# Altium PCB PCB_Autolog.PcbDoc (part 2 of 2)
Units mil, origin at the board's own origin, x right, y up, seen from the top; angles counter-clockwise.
Board outline 3847.36 x 2641.73 mil, 2 copper layers (Top Layer, Bottom Layer); 80 components, 62 nets, 278 pads, 180 vias.
Unrouted connection lines stored in the file: 64.
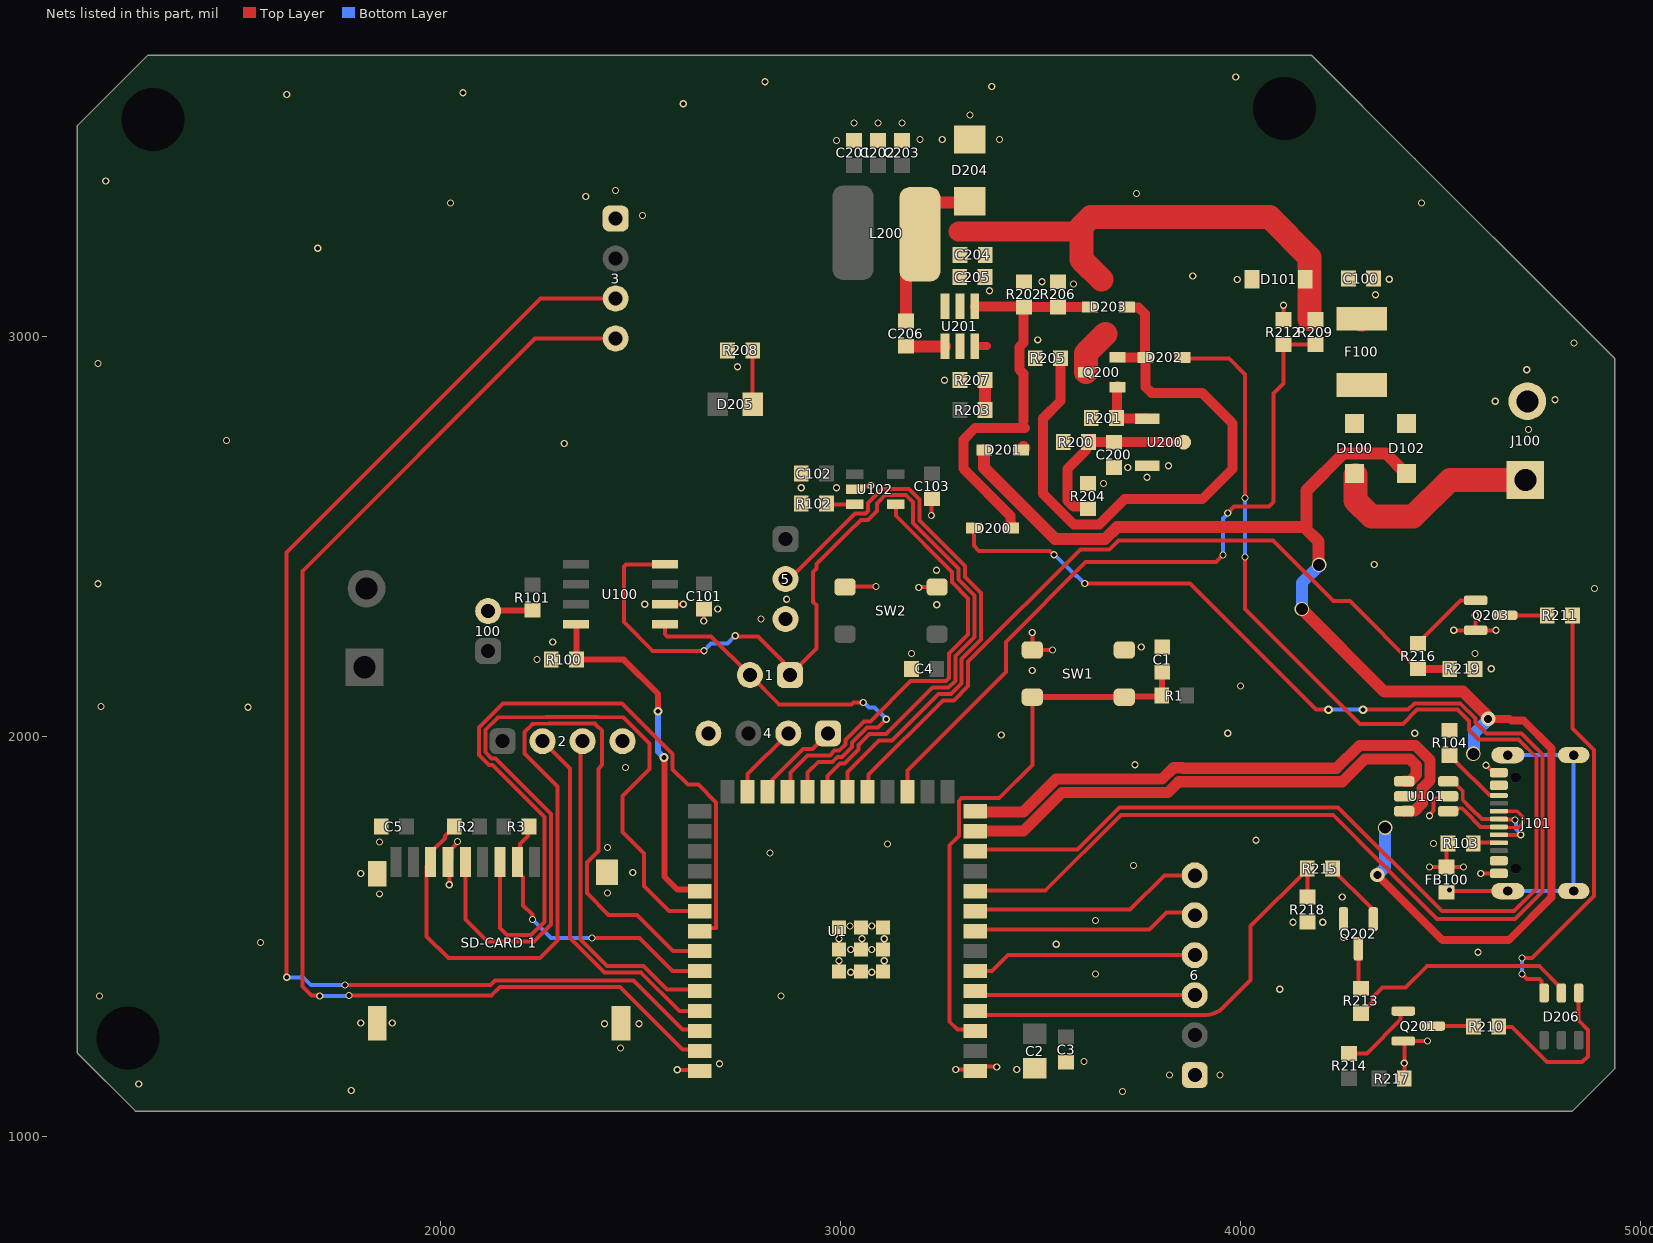
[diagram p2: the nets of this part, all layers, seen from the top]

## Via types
v1: diameter 18, hole 12, Top Layer to Bottom Layer, tented both sides, 162 vias
v2: diameter 22, hole 12, Top Layer to Bottom Layer, tented both sides, 8 vias
v3: diameter 36, hole 30, Top Layer to Bottom Layer, tented both sides, 7 vias
v4: diameter 36, hole 20, Top Layer to Bottom Layer, tented both sides, 2 vias
v5: diameter 37, hole 30, Top Layer to Bottom Layer, tented both sides, 1 vias

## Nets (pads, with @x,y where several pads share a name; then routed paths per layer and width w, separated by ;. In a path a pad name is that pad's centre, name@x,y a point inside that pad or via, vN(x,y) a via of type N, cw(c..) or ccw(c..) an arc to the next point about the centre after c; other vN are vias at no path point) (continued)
CAN_RS: R100.2 U1.31 U100.8 | length 894.3
  Top Layer w15: U100.8@2337.73,2280.71 2338.98,2279.46 R100.2@2338.98,2192.21 2457.39,2192.21 2543.31,2106.3 v2(2543.31,2062.99) ; v2(2557.78,1947.54) 2558.92,1946.4 2558.92,1649.74 2591.73,1616.93 U1.31@2647.64,1616.93
  Bottom Layer w15: v2(2543.31,2062.99) 2543.31,1962.01 v2(2557.78,1947.54)
CAN_RX: 1.1 U1.21 U100.4 | length 2389.2
  Top Layer w10: U100.4@2560.23,2430.71 2463.25,2430.71 2457.39,2424.85 2457.39,2286.7 2529.66,2214.44 v1(2658.21,2214.44) ; v1(2736.22,2251.97) 2737.75,2250.44 2792.87,2250.44 2856.17,2187.14 2856.17,2170.21 1.1@2872.83,2153.54 2939.66,2220.37 2939.66,2328.35 2931.25,2336.75 2931.25,2411.28 2939.66,2419.69 2939.66,2431.73 3015.85,2507.92 3016.4,2507.92 3050.38,2541.9 3068.27,2541.9 3090.55,2564.18 3090.55,2582.68 3111.4,2603.52 3164.01,2603.52 3181.35,2586.18 3181.35,2533.51 3294.72,2420.14 3294.72,2392.51 3334.9,2352.33 3334.9,2248.97 3286.84,2200.91 3286.84,2139.29 3269.85,2122.29 3229.53,2122.29 3113.3,2006.06 3071.95,2006.06 3044.4,1978.5 3044.4,1967.08 3009.69,1932.37 2998.27,1932.37 2967.13,1901.23 U1.21@2967.13,1866.14
  Bottom Layer w10: v1(2658.21,2214.44) 2676.05,2232.28 2716.54,2232.28 v1(2736.22,2251.97)
CAN_TX: 1.2 U1.22 U100.1 | length 973.3
  Top Layer w10: U100.1@2560.23,2280.71 2560.23,2256.3 2566.09,2250.44 2675.94,2250.44 1.2@2772.83,2153.54 2846.32,2080.06 3027.59,2080.06 3032.59,2085.06 3056.43,2085.06 v1(3056.59,2085.22) ; U1.22@2917.13,1866.14 2917.13,1909.45 2944.43,1936.76 2980.03,1936.76 2991.64,1948.37 3003.06,1948.37 3028.4,1973.71 3028.4,1985.13 3065.33,2022.06 3092.92,2022.06 v1(3114.17,2043.31)
  Bottom Layer w10: v1(3056.59,2085.22) 3058.76,2085.22 3071.43,2072.55 3084.93,2072.55 v1(3114.17,2043.31)
FORCE_ON: D200.2 U1.10 | length 3680.4
  Top Layer w10: D200.2@3333.74,2521 3333.74,2477.28 3346.46,2464.57 3523.62,2464.57 v1(3533.6,2454.59) ; U1.10@3336.61,1616.93 3339.37,1614.17 3511.81,1614.17 3700.79,1803.15 4232.28,1803.15 4352.89,1682.54 4354.53,1682.54 4371.52,1665.56 4371.52,1663.91 4492.38,1543.06 4686.95,1543.06 4756.16,1612.27 4756.16,1954.66 4702.95,2007.87 4615.1,2007.87 4588.04,2034.94 4588.04,2044.91 4550.02,2082.93 4435.44,2082.93 4419.44,2066.93 v2(4307.09,2066.93) ; v1(3610.55,2382.39) 3873.52,2382.39 4188.98,2066.93 v2(4220.47,2066.93)
  Bottom Layer w10: v1(3533.6,2454.59) 3535.57,2454.59 3588.65,2401.5 3591.44,2401.5 v1(3610.55,2382.39) ; v2(4220.47,2066.93) v2(4307.09,2066.93)
GND: 2.4 3.1 4.4 5.3 6.1 "SD-CARD 1.6" "SD-CARD 1.10" "SD-CARD 1.11" "SD-CARD 1.12" "SD-CARD 1.13" C1.2 C2.2 C3.2 C4.1 C5.1 C100.1 C101.1 C102.2 C103.2 C200.2 C201.2 C202.2 C203.2 C204.2 C205.2 D101.2 D204.2 FB100.1 J100.2 j101.A1/B12 j101.B1/A12 Q201.2 Q202.2 Q203.2 R100.1 R102.1 R103.1 R104.2 R204.1 R205.1 R206.1 R207.1 R208.2 R212.1 R217.2 R218.1 R219.1 SW1.2 SW2.2 U1.1 U1.40 U1.41 U1.42 U1.43 U1.44 U1.45 U1.46 U1.47 U1.48 U1.49 U100.2 U101.2 U102.2 U200.3 U201.2 | length 1302.6
  Top Layer w10: v1(2020.83,1628.91) 2020.83,1682.92 2017.71,1686.03 2026.49,1694.81 2026.49,1718.43 2039.79,1731.72 2039.79,1735.68 v1(2041.32,1737.21) ; U100.2@2560.23,2330.71 v1(2606.24,2330.71) ; v1(2591,1166) 2641.83,1166 U1.40@2643.83,1164 ; v1(2657.48,2288.63) C101.1@2657.48,2318.9 ; SW2.2@3010.83,2374.02 3011.52,2374.7 3087.89,2374.7 v1(3088.58,2375.39) ; U102.2@3035.43,2618.11 3042.24,2624.92 3070.1,2624.92 3072.87,2627.7 v1(3075.04,2627.7) ; v1(3195.28,2372.77) 3195.9,2373.39 3240.52,2373.39 SW2.2@3241.14,2374.02 ; v1(3226.85,2552.57) 3226.85,2592.98 C103.2@3228.35,2594.48 ; v1(3287.83,1166.93) 3336.61,1166.93 3344.58,1174.9 3388.91,1174.9 v1(3390.58,1173.23) ; v1(3479.33,2260.24) 3479.33,2229.58 3492.38,2216.54 v1(3529.96,2216.54) ; R212.1@4107.48,3043.31 v1(4107.48,3078.71) ; R217.2@4410.04,1144.25 v1(4410.04,1182.75) 4410.04,1235.63 Q201.2@4407.48,1238.19 v1(4468.04,1238.19) ; v1(4472.77,1673.23) FB100.1@4515.75,1673.23 ; v1(4472.77,1801.76) 4472.77,1803.92 4483.09,1814.25 4483.09,1838.98 4489.17,1845.06 4514.35,1845.06 U101.2@4519.69,1850.39 ; R103.1@4519.68,1732.28 4515.75,1728.35 FB100.1@4515.75,1673.23 ; v1(4533.84,2265.75) Q203.2@4588.58,2265.75 ; v1(4558.18,1673.23) FB100.1@4515.75,1673.23 ; v1(4587.68,2303.15) 4587.68,2266.65 Q203.2@4588.58,2265.75 ; v1(4601.24,1657.48) j101.A1/B12@4646.56,1657.48 ; v1(4614.17,1928.25) 4626.72,1915.7 4640.3,1915.7 j101.B1/A12@4646.56,1909.45 ; v1(4639.76,2265.75) Q203.2@4588.58,2265.75
  other v1: 3705,1112 1775.59,1114.17 1244.09,1130.54 3822.83,1152.76 3948.61,1152.76 3440.35,1166.93 2696.85,1181.1 3609,1187 2448.82,1220.47 2409.09,1281.54 2495.7,1281.54 1799.21,1283.46 1877.95,1283.46 1145.67,1350.39 2850.39,1350.39 4098.43,1367.62 3637.8,1405.51 3025,1410 3077.9,1410 2996.06,1439 3109,1439 4594.56,1460.01 3025,1467 3077.9,1467 3539.37,1480.32 1548.42,1484.25 2996.06,1494 3053,1494 3109,1494 4257.87,1496.77 3023,1526 3077.9,1525.98 4131.32,1535.43 4205.82,1535.43 3637.8,1539.37 4254.82,1598.43 1846.46,1606.3 2416.96,1608.32 1799.21,1657.48 2479.95,1659.5 3732.34,1677.17 2822.83,1708.66 2416.6,1722.49 3117.13,1731.06 4483.09,1732.28 1846.46,1735.68 4039.37,1740.16 2461.39,1922.39 3736.22,1929.13 3401.57,2003.94 3968.5,2007.87 4436.18,2007.87 1517,2073 1149.61,2074.8 4000,2125.98 3479.33,2165.35 4627.63,2169.29 2240.16,2192.91 3177.16,2207.54 4586.62,2207.79 3751.91,2223.98 2279.59,2236.28 2801.02,2293.7 2692.32,2318.9 3240.16,2329.6 2509.64,2330.97 2864.85,2343.4 4885.83,2370.08 1141.73,2381.89 3239.94,2415.79 4334.72,2430.28 2901.57,2622.11 2989.54,2622.11 3657.27,2632.72 3766.35,2648.72 3718.41,2673.22 3820.22,2677.22 2308.62,2732.65 1463.62,2740.65 4720.54,2767.72 4637.8,2838.58 4787.4,2842.58 3259.84,2891.22 4716.54,2917.32 2741.65,2925.2 1141.73,2933.07 4834.65,2984.25 3492.87,2992.26 4338.36,3104.87 3372,3115 3582.45,3131.93 3503.94,3137.72 3992,3143 4372.2,3143.89 3880.69,3152.08 1691.62,3221.65 2503.94,3303.15 2023.62,3334.65 4452.76,3334.65 2362.2,3350.67 3740.16,3358.27 2437.01,3366.14 1161.42,3389.76 2989.42,3491.22 3198.27,3493.58 3254.34,3493.58 3397.64,3493.58 3033.27,3535.02 3093.27,3535.02 3153.27,3535.02 3323.27,3555.12 2606.3,3582.68 1614.17,3606.3 2055.12,3610.24 3377.95,3625.98 2811.02,3637.8 3988.19,3649.61
GPIO47: 4.1 U1.24 | length 218.6
  Top Layer w10: U1.24@2817.13,1866.14 2829.84,1878.86 2829.84,1892.65 2905.69,1968.5 2909.45,1968.5 2909.7,1968.76 2929.78,1968.76 4.1@2968.9,2007.87
GPIO48: 4.2 U1.25 | length 183.9
  Top Layer w10: U1.25@2767.13,1866.14 2767.13,1906.1 4.2@2868.9,2007.87
GPIO_5: 6.3 U1.5 | length 555.1
  Top Layer w10: U1.5@3336.61,1366.93 3349.33,1354.21 3365.54,1354.21 3367,1352.76 6.3@3885.83,1352.76
GPIO_6: 6.4 U1.6 | length 565.7
  Top Layer w10: U1.6@3336.61,1412.93 3379.15,1412.93 3418.98,1452.76 6.4@3885.83,1452.76
GPIO_12: 5.2 U1.20 | length 1417.1
  Top Layer w10: 5.2@2862.2,2393.7 2871.72,2393.7 3035.92,2557.9 3061.64,2557.9 3068.08,2564.34 3068.08,2583.83 3103.77,2619.52 3170.64,2619.52 3197.35,2592.81 3197.35,2540.14 3310.72,2426.77 3310.72,2399.14 3350.9,2358.96 3350.9,2242.34 3302.84,2194.28 3302.84,2132.66 3276.47,2106.29 3244.53,2106.29 3128.3,1990.06 3096.35,1990.06 3017.13,1910.83 U1.20@3017.13,1866.14
GPIO_15: 6.5 U1.8 | length 569.3
  Top Layer w10: U1.8@3336.61,1516.93 3772.83,1516.93 3814.96,1559.06 3879.53,1559.06 6.5@3885.83,1552.76
GPIO_16: 6.6 U1.9 | length 581.3
  Top Layer w10: U1.9@3340.12,1566.93 3724.41,1566.93 3810.24,1652.76 6.6@3885.83,1652.76
GREEN_LED: R215.1 R218.2 U1.4 | length 1134.6
  Top Layer w10: U1.4@3336.61,1316.93 3350.73,1302.81 3568.66,1303.44 cw(c3568.78,1262.91) 3575.9,1302.81 3906.55,1302.81 ccw(c3906.55,1382.85) 3948.61,1314.76 4025,1391.14 4025,1525.47 R215.1@4167.32,1667.79 ; R218.2@4167.32,1598.43 R215.1@4167.32,1667.79 ; R215.1@4167.32,1669.29 R215.1@4167.32,1667.79
H_DRIVER: U1.23 U102.4 | length 1077.3
  Top Layer w10: U1.23@2867.13,1866.14 2874.02,1873.03 2874.02,1909.45 2917.32,1952.76 2973.4,1952.76 2985.02,1964.37 2996.43,1964.37 3012.4,1980.34 3012.4,1991.75 3058.7,2038.06 3074.48,2038.06 3174.72,2138.29 3263.22,2138.29 3270.84,2145.92 3270.84,2207.54 3318.9,2255.59 3318.9,2345.71 3278.72,2385.89 3278.72,2411.66 3137.8,2552.57 U102.4@3137.8,2580.71
Net100_2: 100.2 R101.1 | length 111.7
  Top Layer w15: 100.2@2118.11,2313.78 2119.08,2314.75 2228.01,2314.75 R101.1@2228.98,2315.71
NetC1_1: C1.1 R1.1 SW1.1 U1.3 | length 1410.3
  Top Layer w10: U1.3@3336.61,1266.93 3292.13,1266.93 3271.65,1287.4 3271.65,1726.77 3296.09,1751.2 3296.09,1839.2 3302.53,1845.65 3370.7,1845.65 3370.86,1845.49 3396.67,1845.49 3479.33,1928.15 SW1.1@3479.33,2098.43
  Top Layer w15: SW1.1@3479.33,2098.43 SW1.1@3709.65,2098.43 3711.67,2100.45 3800.96,2100.45 R1.1@3802.99,2102.48 3803.74,2103.23 3803.74,2160.23 C1.1@3804.49,2160.98
NetC200_1: C200.1 R200.1 R204.2 U200.2 | length 466.2
  Top Layer w25: R204.2@3618.27,2569.72 3612.9,2575.09 3582.1,2575.09 3566.93,2590.26 3566.93,2669.29 3613.77,2716.13 3613.77,2730.22 R200.1@3619.77,2736.22 3629.92,2736.22 C200.1@3683.27,2736.22 U200.2@3858.27,2736.22
NetC206_1: C206.1 U201.1 | length 97.6
  Top Layer w30: C206.1@3163.27,2976.22 U201.1@3260.85,2976.24
NetC206_2: C206.2 D204.1 L200.1 U201.6 | length 416.9
  Top Layer w30: C206.2@3163.27,3039.22 3163.27,3148.56 3198.27,3183.56 L200.1@3198.27,3256.22 3198.27,3300.92 3233.64,3336.3 3320.71,3336.3 D204.1@3323.27,3338.86
NetD100_1: D100.1 D102.1 F100.2
NetD100_2: D100.2 J100.1 | length 543
  Top Layer w60: D100.2@4288.31,2653.7 4288.31,2589.84 4328.15,2550 4432.24,2550 4523.98,2641.73 J100.1@4712.91,2641.73
NetD200_1: D200.1 D201.1 D203.1 R202.1 R206.2 U201.4 | length 1013.6
  Top Layer w25: U201.4@3335.67,3076.19 3455.36,3076.19 R202.1@3456.8,3074.75 ; D200.1@3426.06,2521 3425.99,2522.28 3424.42,2552.4 3307,2669.82 3307,2742.37 3336.28,2771.65 3460.63,2771.65 ; 3456.8,2789.23 3456.8,2907.99 3447.27,2917.52 3447.27,2974.92 3456.8,2984.45 R202.1@3456.8,3071.22 ; R202.1@3458.27,3074.72 R206.2@3543.27,3074.72 D203.1@3620.08,3074.72
  Top Layer w30: D201.1@3456.8,2724.32 D201.1@3459.9,2721.22
NetD202_1: D202.1 D203.2 Q200.2 R205.2 | length 1594.2
  Top Layer w25: R205.2@3549.77,2946.22 3549.77,2839.07 3505.77,2795.07 3505.77,2607.58 3583.13,2530.22 3646.97,2530.22 3710.6,2593.85 3904.88,2593.85 3980.32,2669.29 3980.32,2783.46 3903.98,2859.8 3777.33,2859.8 3762.69,2874.44 D202.1@3762.69,2948.62 3761.41,2949.9 3761.29,2949.9 3761.29,3057.12 3744.97,3073.44 D203.2@3730.41,3073.44 ; Q200.2@3692.64,2948.62 D202.1@3759.24,2948.62 ; D203.2@3716.08,3073.44 D203.2@3730.41,3073.44 ; D203.2@3729.13,3074.72 D203.2@3730.41,3073.44
NetD205_2: D205.2 R208.1 | length 135.3
  Top Layer w10: D205.2@2779.53,2830.71 2779.84,2831.02 2779.84,2965.39 R208.1@2780.15,2965.7
NetD206_1: D206.1 R210.1 | length 433.9
  Top Layer w10: R210.1@4646.26,1274.17 4647.76,1272.67 4679.8,1272.67 4767.43,1185.04 4854.33,1185.04 4869.27,1199.98 4869.27,1266.17 4846.46,1288.98 D206.1@4846.46,1358.27
NetD206_2: D206.2 R213.1 | length 592.4
  Top Layer w10: R213.1@4301.18,1307.08 4302.68,1307.08 4330.95,1335.35 4330.95,1345.8 4332.18,1347.03 4332.18,1347.93 4356.06,1371.8 4412.86,1371.8 4466.25,1425.2 4696.13,1425.2 4696.44,1425.51 4713.01,1425.51 4713.32,1425.2 4748.03,1425.2 4803.15,1370.08 D206.2@4803.15,1358.27
NetD206_3: D206.3 R211.1 | length 1096.6
  Top Layer w10: v1(4704.72,1405.51) 4716.54,1393.7 4747.73,1393.7 4753.59,1387.84 4753.59,1364.52 D206.3@4759.84,1358.27 ; v1(4704.72,1445.51) 4728.97,1445.51 4884.13,1600.68 4884.13,1966.25 4830.71,2019.67 R211.1@4830.71,2303.15
  Bottom Layer w10: v1(4704.72,1405.51) v1(4704.72,1445.51)
NetFB100_2: FB100.2 j101.0 | length 824
  Top Layer w10: FB100.2@4515.75,1610.23 4518.9,1613.39 j101.0@4669.19,1613.39
  Bottom Layer w10: j101.0@4669.19,1613.39 j101.0@4833.76,1613.39 j101.0@4833.76,1953.54 j101.0@4669.19,1953.54
  other v1: 4522.9,1615.75
Netj101_A5: j101.A5 R103.2 | length 64.7
  Top Layer w10: R103.2@4582.68,1732.28 4584.65,1734.25 j101.A5@4646.56,1734.25
Netj101_B5: j101.B5 R104.1 | length 165.4
  Top Layer w10: R104.1@4523.62,1952.75 4525.12,1952.75 4538.62,1939.25 4538.62,1937.75 4623.11,1853.27 4645.65,1853.27 j101.B5@4646.56,1852.36
NetQ200_1: Q200.1 R201.2 U200.1 | length 156.3
  Top Layer w25: R201.2@3690.24,2795.74 3766.35,2795.74 U200.1@3766.83,2795.26 ; R201.2@3691.2,2797.66 Q200.1@3691.2,2872.39
  Top Layer w30: R201.2@3690.24,2795.74 R201.2@3689.77,2796.22 R201.2@3691.2,2797.66 ; Q200.1@3691.2,2872.39 Q200.1@3692.64,2873.82
NetQ201_1: Q201.1 R214.2 | length 187.5
  Top Layer w10: R214.2@4272.24,1207.25 4316.23,1207.25 4401.02,1292.04 4401.02,1306.53 Q201.1@4407.48,1312.99
NetQ201_3: Q201.3 R210.2 | length 101.6
  Top Layer w10: Q201.3@4482.28,1275.59 4581.85,1275.59 R210.2@4583.26,1274.17
NetQ202_1: Q202.1 R215.2 | length 168.4
  Top Layer w10: R215.2@4230.32,1669.29 4230.32,1667.79 4326.43,1571.69 4326.43,1549.56 Q202.1@4332.68,1543.31
NetQ202_3: Q202.3 R213.2 | length 100.9
  Top Layer w10: Q202.3@4295.28,1468.5 4295.28,1375.99 R213.2@4301.18,1370.08
NetQ203_1: Q203.1 R216.2 | length 190.5
  Top Layer w10: R216.2@4444.88,2232.29 4446.38,2232.29 4459.88,2245.79 4459.88,2249.14 4550.39,2339.65 4587.68,2339.65 Q203.1@4588.58,2340.55
NetQ203_3: Q203.3 R211.2 | length 104.3
  Top Layer w10: Q203.3@4663.39,2303.15 R211.2@4767.71,2303.15
NetR102_2: R102.2 U102.3 | length 71.7
  Top Layer w10: R102.2@2964.57,2582.68 2966.53,2580.71 U102.3@3035.43,2580.71
NetR203_1: R203.1 R207.2 U201.3 | length 105.3
  Top Layer w20: U201.3@3335.8,2976.38 3366.14,2976.38
  Top Layer w30: R203.1@3361.27,2816.22 R207.2@3361.27,2891.22
RED_LED: R216.1 R219.2 U1.19 | length 1905
  Top Layer w10: U1.19@3067.13,1866.14 3070.17,1869.18 3070.17,1904.81 3255.65,2090.29 3283.1,2090.29 3318.84,2126.03 3318.84,2187.66 3599.41,2468.22 3672.65,2468.22 3694.74,2490.32 4081.43,2490.32 4233.16,2338.58 4274.09,2338.58 4443.38,2169.29 R216.1@4444.88,2169.29
  Top Layer w20: R216.1@4444.88,2169.29 R219.2@4523.62,2169.29
RXD: 2.3 U1.36 | length 848.5
  Top Layer w10: 2.3@2354.33,1988.19 2349,1982.86 2349,1492.53 2415.57,1425.95 2506.5,1425.95 2565.52,1366.93 U1.36@2647.64,1366.93
SCL: 3.3 U1.38 | length 3246.3
  Top Layer w10: v1(1614.17,1397.64) 1614.17,2460.63 2249.21,3095.67 3.3@2437.01,3095.67 ; v1(1759.84,1377.95) 2123.81,1377.95 2135.62,1389.76 2481.24,1389.76 2604.07,1266.93 U1.38@2647.64,1266.93
  Bottom Layer w10: v1(1614.17,1397.64) 1654.59,1397.64 1674.28,1377.95 v1(1759.84,1377.95)
SD_CARD: "SD-CARD 1.2" R3.1 U1.35 | length 737.7
  Top Layer w10: R3.1@2220.23,1779.86 2217.8,1777.43 2217.8,1750.72 2198.22,1731.14 2198.22,1693.3 2190.94,1686.03 2190.94,1662.4 2205.47,1647.88 2205.47,1577.66 2228.69,1554.44 2228.69,1542.65 v1(2229.02,1542.32) ; v1(2377.98,1495.81) 2496.34,1495.81 2579.22,1412.93 U1.35@2647.64,1412.93
  Bottom Layer w10: v1(2229.02,1542.32) 2275.52,1495.81 v1(2377.98,1495.81)
SDA: 3.4 U1.39 | length 3142.5
  Top Layer w10: v1(1696.85,1350.39) 1695.32,1351.92 1675.63,1351.92 1653.54,1374.02 1653.54,2413.39 2235.83,2995.67 3.4@2437.01,2995.67 ; v1(1769.66,1351.92) 2125.84,1351.92 2147.68,1373.76 2448.01,1373.76 2604.85,1216.93 U1.39@2647.64,1216.93
  Bottom Layer w10: v1(1696.85,1350.39) 1697.62,1351.16 1768.9,1351.16 v1(1769.66,1351.92)
SEN_ANALOG: R209.1 R212.2 U1.17 | length 1826.1
  Top Layer w10: U1.17@3167.13,1866.14 3167.13,1915.16 3413.39,2161.42 3413.39,2236.95 3612.66,2436.22 3938.6,2436.22 v1(3956.69,2454.32) ; v1(3968.5,2559.06) 3984.25,2574.8 4071.15,2574.8 4082.68,2586.33 4082.68,2858.27 4107.48,2883.07 4107.48,2978.81 4108.98,2980.31 R209.1@4188.98,2980.31
  Bottom Layer w10: v1(3956.69,2454.32) 3956.69,2545.08 3968.5,2556.89 v1(3968.5,2559.06)
SEN_DIGITAL: D202.2 U1.12 | length 3592.8
  Top Layer w10: U1.12@3336.61,1716.93 3591.94,1716.93 3697.84,1822.83 4244.09,1822.83 4503.94,1562.99 4684.26,1562.99 4740.16,1618.89 4740.16,1948.04 4696.32,1991.87 4596.18,1991.87 4572.04,2016.02 4572.04,2038.28 4543.39,2066.93 4442.07,2066.93 4406.64,2031.5 4299.48,2031.5 4011.81,2319.16 v1(4011.81,2448.82) ; D202.2@3855.01,2948.62 3857.41,2946.22 3971.1,2946.22 4011.81,2905.51 v1(4011.81,2596.63)
  Bottom Layer w10: v1(4011.81,2448.82) v1(4011.81,2596.63)
TCK_SCK: "SD-CARD 1.5" U1.32 | length 1981.4
  Top Layer w10: 2061.02,1686.03 2061.02,1542.32 2116.34,1487 2232.24,1487 2275.03,1529.79 2275.03,1805.53 2135.88,1944.69 2126.79,1944.69 2110.83,1960.65 2110.83,2015.73 2139.86,2044.76 2142.79,2047.69 2263.25,2048.19 2392.04,2048.19 2456.35,2047.69 2459.28,2044.76 2521.59,1982.45 2521.59,1919.22 2453.91,1851.55 2453.91,1760.65 2507.87,1706.69 2507.87,1625.98 2570.93,1562.93 U1.32@2647.64,1562.93
TDI_MISO: "SD-CARD 1.7" R2.1 U1.34 | length 2197.6
  Top Layer w10: R2.1@2033.37,1774.6 2009.94,1751.17 2009.94,1745.26 1983.1,1718.43 1974.41,1686.03 1964.39,1676 1964.39,1500.02 2018.4,1446 2248,1446 2291.03,1489.03 2291.03,1874.74 2208.78,1956.99 2208.78,2010.78 2226.12,2028.12 2228.92,2030.92 2232.88,2031.04 2269.72,2032.19 2269.88,2032.19 2385.42,2032.19 2388.35,2029.27 2402.82,2014.79 2402.82,1929.37 2400.66,1926.63 2395.74,1920.44 2393.57,1917.71 2393.57,1914.22 2393.57,1713.27 2365,1684.69 2365,1607.94 2419.55,1553.38 2490.62,1553.38 2581.07,1462.93 U1.34@2647.64,1462.93
TDO_MOSI: "SD-CARD 1.3" U1.33 | length 1957.8
  Top Layer w10: 2147.64,1686.03 2147.64,1520.66 2165.31,1503 2225.61,1503 2259.03,1536.42 2259.03,1798.91 2129.25,1928.69 2120.17,1928.69 2094.83,1954.02 2094.83,2022.35 2155.45,2082.97 2453.46,2082.97 2579.78,1956.65 2579.78,1917.67 2618.12,1879.32 2644.04,1879.32 2688.17,1835.2 2688.17,1520.5 2651.2,1520.5 U1.33@2647.64,1516.93
TXD: 2.2 U1.37 | length 921.2
  Top Layer w10: 2.2@2254.33,1988.19 2323.09,1919.43 2323.09,1495.81 2408.94,1409.95 2499.87,1409.95 2596.89,1312.93 U1.37@2647.64,1312.93
USB_D_N: U1.13 U101.4 | length 1239.6
  Top Layer w28: U1.13@3342.52,1763.78 3457.53,1763.78 3553.4,1859.65 3818.34,1859.65 3845.34,1886.65 4254.7,1886.65 4311.85,1943.8 4423.69,1943.8 4440.09,1927.39 4440.09,1904.2 4423.69,1887.8 U101.4@4409.45,1887.8
USB_D_P: U1.14 U101.6 | length 1390.8
  Top Layer w28: U1.14@3338.58,1811.02 3456.69,1811.02 3539.32,1893.65 3804.26,1893.65 3832.41,1921.8 3855.21,1921.8 3856.36,1920.65 4240.62,1920.65 4297.77,1977.8 4437.78,1977.8 4474.09,1941.48 4474.09,1890.11 4455.04,1871.06 4455.04,1833.05 4436.18,1814.2 4410.65,1814.2 U101.6@4409.45,1812.99
USBC_N: j101.A7 j101.B7 U101.3 | length 318.9
  Top Layer w10: U101.3@4519.69,1887.8 4532.48,1887.8 4556.28,1864 4556.28,1841.22 4577.32,1820.17 4604.19,1793.31 j101.A7@4646.56,1793.31 4647.46,1792.4 4685.85,1792.4 v1(4687.27,1790.98) ; j101.B7@4646.56,1753.94 4646.63,1754.01 4701.46,1754.01 v1(4701.54,1754.08)
  Bottom Layer w10: v1(4687.27,1790.98) 4689.75,1788.5 4689.75,1768.04 4701.54,1756.25 v1(4701.54,1754.08)
USBC_P: j101.A6 j101.B6 U101.1 | length 295.7
  Top Layer w8: j101.A6@4624.02,1773.62 j101.A6@4646.56,1773.62 4648.2,1771.98 4695.14,1771.98 4706.27,1783.11 4706.27,1798.88 4692.16,1812.99 j101.B6@4646.56,1812.99
  Top Layer w10: U101.1@4519.69,1812.99 4532.48,1812.99 4539.41,1819.92 4545.61,1819.92 4546.13,1820.45 4554.42,1820.45 4561.32,1813.55 4601.24,1773.62 j101.A6@4624.02,1773.62
VBUSS: D102.2 D201.2 j101.A4/B9 j101.B4/A9 U101.5 | length 3494.7
  Top Layer w20: v4(4342.52,1653.54) 4505.61,1490.45 4671.11,1490.45 4778.39,1597.73 4778.39,1969.64 4708.66,2039.37 4677.9,2039.37 4673.19,2044.08 v4(4619.9,2044.08)
  Top Layer w30: D201.2@3358.91,2717.28 3358.91,2671.65 3492.72,2537.84 3536.34,2494.22 3661.88,2494.22 3691.28,2523.62 4159.79,2523.62 ; v3(4153.54,2318.9) 4360.15,2112.29 4557.43,2112.29 4614.04,2055.68 4614.04,2051.57 4619.9,2045.71 v4(4619.9,2044.08) ; v3(4196.85,2429.13) 4195.7,2430.28 4195.7,2487.71 4159.79,2523.62 ; D102.2@4414.45,2657.48 4363.4,2708.53 4258.63,2708.53 4165.35,2615.25 4165.35,2529.18 4159.79,2523.62
  Bottom Layer w30: v3(4153.54,2318.9) 4153.54,2384.2 4196.85,2427.51 v3(4196.85,2429.13) ; v4(4342.52,1653.54) 4362.2,1673.23 v3(4362.2,1771.65) ; v3(4582.68,1956.69) 4583.83,1957.84 4583.83,2006.38 4619.9,2042.46 v4(4619.9,2044.08)
VCC: C100.2 C204.1 C205.1 D101.1 F100.1 Q200.3 R200.2 R201.1 R202.2 R209.2 U201.5 | length 1355.3
  Top Layer w50: 3295.33,3262.9 3602.36,3262.9
  Top Layer w60: Q200.3@3613.9,2911.22 3613.9,2958.64 3662.7,3007.44 ; 3652.16,3142.95 3602.36,3192.75 3602.36,3262.9 3602.36,3275.59 3625.98,3299.21 4072.8,3299.21 4173.36,3198.66 R209.2@4173.36,3044.68 ; F100.1@4301.85,3043.31 ccw(c4301.85,3044.68) F100.1@4303.21,3044.68
pads on no net: "SD-CARD 1.1" "SD-CARD 1.8" "SD-CARD 1.9" j101. j101.A8 j101.B8 U1.7 U1.11 U1.15 U1.16 U1.26 U1.28 U1.29 U1.30 U100.5

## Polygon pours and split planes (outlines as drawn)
GND on Bottom Layer "GND_BOT" (solid, remove dead copper, pour order 1): 1070.86,1063 1000,1133.86 1000,3547.24 1157.48,3704.72 4173.23,3704.72 4937.01,2940.94 4937.01,1169.29 4830.72,1063
GND on Top Layer "GND_TOP" (solid, remove dead copper, pour order 0): 1100.15,1070.52 1100.15,3535.07 1277.32,3712.24 4194.76,3712.24 4951,2956 4951,1161.51 4860.01,1070.52

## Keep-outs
Keep-Out Layer:
  lines w30: 4937.01,2940.94 4937.01,1169.29 4830.72,1063 1235.66,1063 1089.65,1209.01 1089.65,3524.06 1270.31,3704.72 4173.23,3704.72 4937.01,2940.94 ; 4937.01,2940.94 4937.01,2940.94

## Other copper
Top Layer:
  region net TDO_MOSI: 2649.61,1500 2692.91,1500 2692.91,1531.5 2645.67,1531.5
  region net 3V3: 1708.66,1807.09 1708.66,1854.33 1822.83,1854.33 1822.83,1807.09
  region net 3V3: 2066.93,1751.78 2173.56,1751.78 2173.56,1845.23 2066.93,1845.23
  region net 3V3: 2637.8,2452.76 2677.17,2452.76 2677.17,2448.82 2677.17,2385.83 2637.8,2385.83
  region net 3V3: 3724.41,1283.46 3787.4,1283.46 3787.4,1236.22 3724.41,1236.22
  region net 3V3: 4751.97,1263.78 4854.33,1263.78 4854.33,1220.47 4751.97,1220.47
  region net GND: 2975.7,1544.92 3126,1544.92 3126,1385.08 2975.7,1385.08
  region net VCC: 4144.95,3166.19 4300.4,3166.19 4300.4,3014 4151.6,3014 cw(c4151.6,3020.34) 4145.25,3020.34
  region net VCC: 3645.67,3030.92 ccw(c3622.57,3064.57) 3662.7,3057.12 3660.95,3104.86 ccw(c3638.75,3092.88) 3638.67,3118.11 cw(c3653.61,3143.2) 3682.07,3149.71 3692.59,3007.36 cw(c3675.84,3006.12) 3675.84,2989.33
  region net NetC206_2: 3271.65,3047.24 3271.65,3106.3 3267.72,3110.24 3149.61,3110.24 3149.61,3027.56 3181.1,3027.56 3181.1,3043.31 3181.1,3047.24 3259.84,3047.24
  region net NetD100_1: 4259.84,2889.76 4354.33,2889.76 4354.33,2881.89 4354.33,2811.02 4440.94,2811.02 4440.94,2759.84 4259.84,2759.84
  region net NetD200_1: 3440.94,2700.79 3476.38,2700.79 3476.38,2814.96 3440.94,2814.96
  region net NetR203_1: 3346.46,2874.02 3377.95,2874.02 3377.95,2988.19 3346.46,2988.19
  region net CAN_RX: 2872.73,2153.54 2880.6,2145.67 2892.41,2145.67 2904.22,2157.48 2904.22,2224.41 2900.29,2228.35 2845.17,2228.35 2845.17,2153.54 2884.54,2153.54
  region net BOOT: 3220.47,2271.65 3259.84,2271.65 3259.84,2161.42 3220.47,2161.42
  region net VCC: 3287.4,3047.24 3307.09,3047.24 3307.09,3255.91 3287.4,3255.91
  region net VCC: 3547.24,2720.47 3574.8,2720.47 3574.8,2775.59 3645.67,2775.59 3645.67,2925.2 3594.49,2925.2 3594.49,2811.02 3586.61,2803.15 3547.24,2803.15 3547.24,2723.62
  region net VCC: 3476.38,3118.11 3437.01,3118.11 3437.01,3234.65 3438.09,3235.73 3438.09,3286.32 3480.12,3286.32
  region net VBUSS: 4421.26,1862.2 4346.46,1862.2 4346.46,1771.65 4358.27,1759.84 4370.08,1759.84 4374.02,1763.78 4374.02,1838.58 4417.32,1838.58 4421.26,1842.52
  region net VBUSS: 4661.42,1877.95 4663.39,1872.05 4625.98,1874.02 4574.8,1918.37 4574.8,1964.57 4578.74,1968.5 4590.55,1968.5 4590.55,1925.2 4637.8,1877.95
  region net VBUSS: 4649.61,1877.95 4728.35,1877.95 4728.35,1688.98 4645.67,1688.98 4645.67,1696.85 4716.54,1696.85 4716.54,1870.08 4649.61,1870.08

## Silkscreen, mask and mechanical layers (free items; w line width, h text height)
Top Overlay:
  drawing of 233 lines, arcs and shapes, not listed
  text "Nath" at 3837.56,3503.41 h140
  text "MR7" at 3795.52,3392.33 h160
  text "I2C" at 2541.5,3356.94 h60 r270
  text "GND" at 2267.72,3287.4 h30
  text "3v3" at 2267.72,3177.17 h30
  text "SCL" at 2267.72,3043.31 h30
  text "GND" at 4730.16,2958.82 h40 r90
  text "SDA" at 2259.84,2940.55 h30
  text "3v3 GPIO12 GND" at 2926.57,2548.7 h25 r270
  text "VCC (12V)" at 4561.18,2478.5 h40
  text "BOOT" at 3061.18,2425.79 h40
  text "L   H" at 1551.31,2346.33 h40 r270
  text "CAN" at 1484.38,2326.65 h40 r270
  text "canH 120ohm" at 2051.06,2141.86 h30 r90
  text "RX" at 2950.94,2128.11 h60
  text "TX" at 2596.61,2124.17 h60
  text "3v3 TXD RXD GND" at 2129.92,2055.12 h25
  text "USBC" at 4806.07,2004.06 h30 r90
  text "RESET" at 3506.06,2002.13 h40
  text "UART" at 1832.83,1962.76 h60
  text "AuToLOG" at 1181,1925.88 h70 r270
  text "GND 3.3sw 48 47" at 2644.8,1908.57 h35
  text "GND  3V3  GPIO5  6  15   16" at 4022.91,1106.3 h70 r90
BoardShape:
  the board outline again, w30

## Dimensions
1070.87,3527.56 to 4951,2956 on BoardShape
1279.17,3724.41 to 1244.53,1047.24 on BoardShape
